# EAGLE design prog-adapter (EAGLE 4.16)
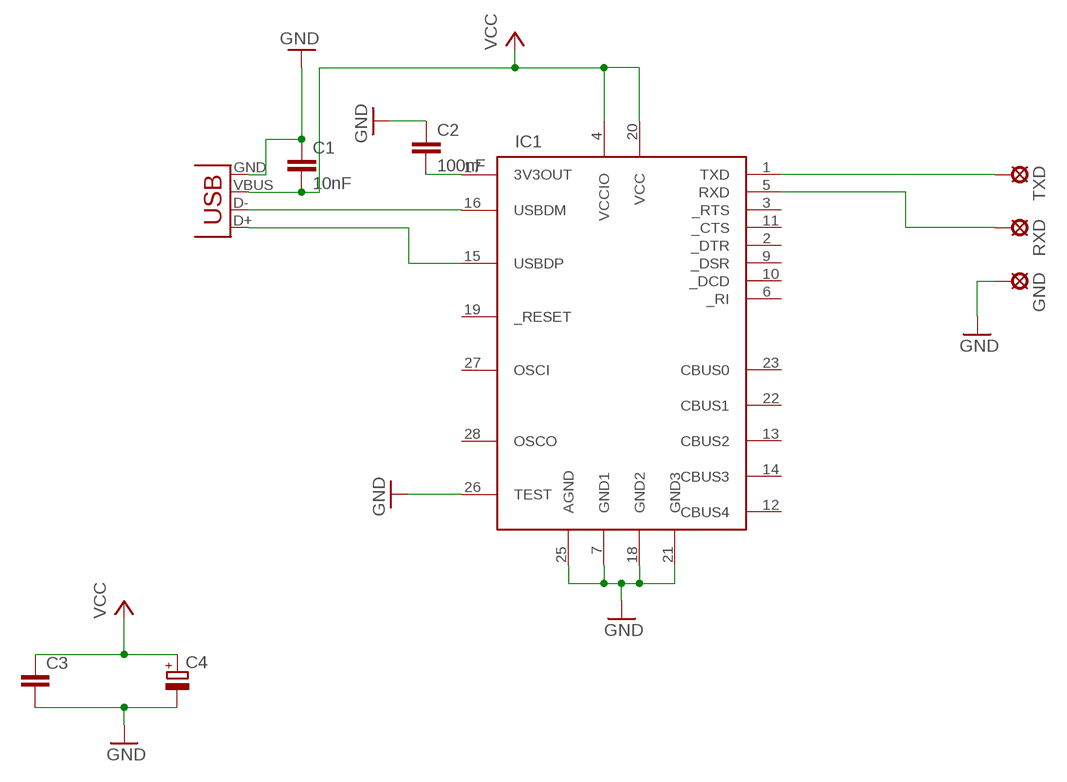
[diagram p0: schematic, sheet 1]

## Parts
C1  10nF  C-EUC1206  [C1206]
C2  100nF  C-EUC1206  [C1206]
C3  C-EUC1206  [C1206]
C4  CPOL-EUSMCC  [SMC_C]
GND  LSP10  [LSP10]
IC1  FT232RL  [SSOP28DB]
RXD  LSP10  [LSP10]
TXD  LSP10  [LSP10]
X1  USB-MB-S  [USB-MB-S]

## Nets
GND: C1.1 C2.1 C3.2 C4.- GND.MP IC1.7(GND1) IC1.18(GND2) IC1.21(GND3) IC1.25(AGND) IC1.26(TEST) X1.GND
N$1: IC1.16(USBDM) X1.D-
N$2: IC1.15(USBDP) X1.D+
N$3: IC1.1(TXD) TXD.MP
N$4: IC1.5(RXD) RXD.MP
N$6: C2.2 IC1.17(3V3OUT)
VCC: C1.2 C3.1 C4.+ IC1.4(VCCIO) IC1.20(VCC) X1.VBUS
Unconnected: IC1.2(_DTR) IC1.3(_RTS) IC1.6(_RI) IC1.9(_DSR) IC1.10(_DCD) IC1.11(_CTS) IC1.12(CBUS4) IC1.13(CBUS2) IC1.14(CBUS3) IC1.19(_RESET) IC1.22(CBUS1) IC1.23(CBUS0) IC1.27(OSCI) IC1.28(OSCO)

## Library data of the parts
C1-C3 = rcl:C-EU: CAPACITOR, European symbol
C4 = rcl:CPOL-EU: POLARIZED CAPACITOR, European symbol
GND RXD TXD = solpad:LSP10: SOLDER PAD
IC1 = ftdichip:FT232RL: USB UART 4th Generation USB UART (USB <-> Serial) Controller
X1 = con-usb:USB: USB Connectors

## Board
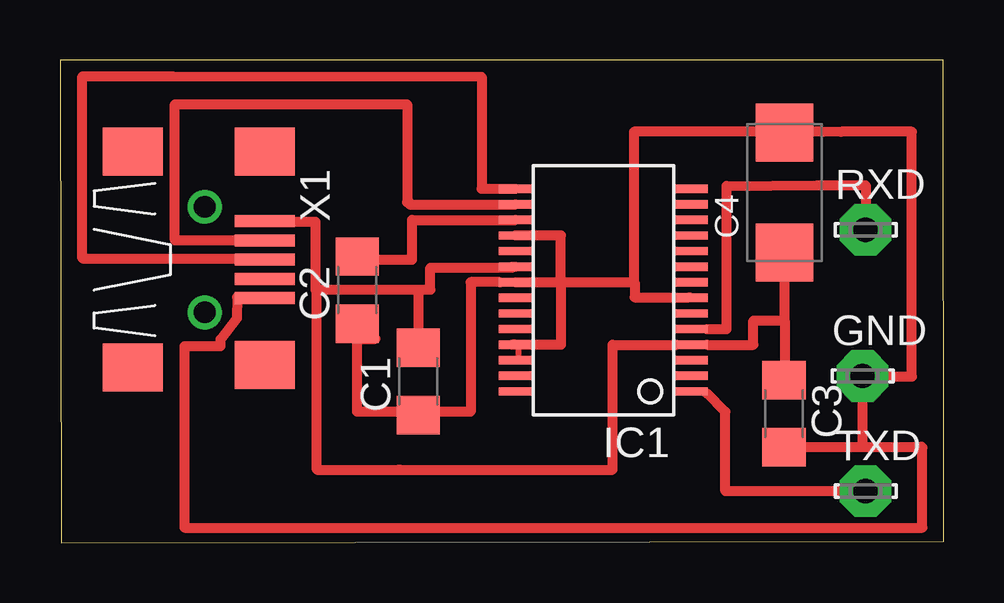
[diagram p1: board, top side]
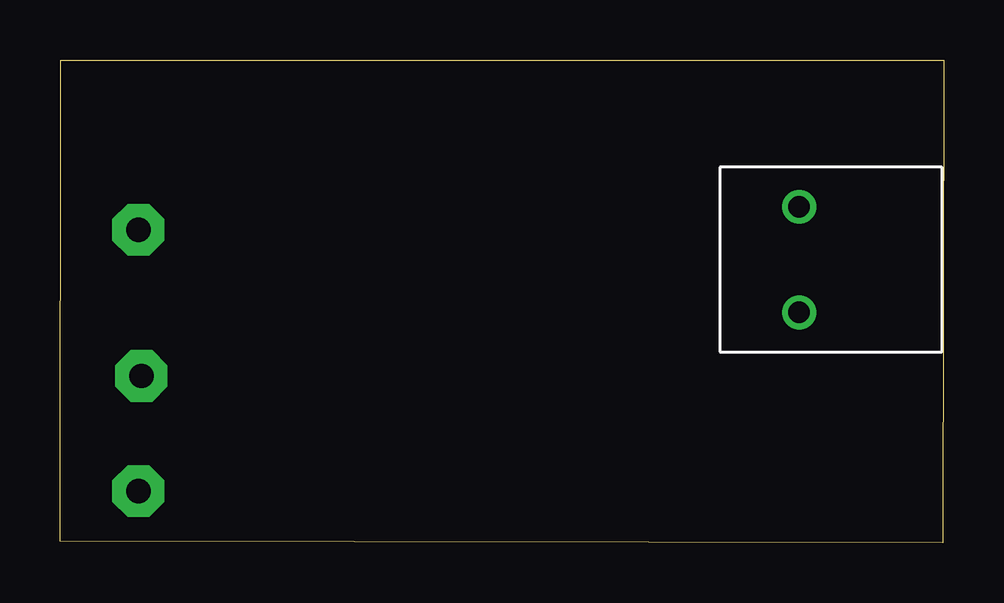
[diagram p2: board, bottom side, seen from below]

Size 36.83 x 20.13 mm. Coordinates in mm from the lower left corner, seen from the top.
Outline: 0.05,0 36.83,0.05 36.8,20.13 0,20.13 0.05,0
Copper layers (1*16): Top 0.035mm / dielectric 1.5mm / Bottom 0.035mm
Design rules "default": minimum track width 10mil, minimum drill 24mil, track to track 8mil, track to pad 8mil, pad to pad 8mil, via to via 8mil, smd to smd 8mil, copper to edge 40mil, drill to drill 8mil, minimum pad ring 10mil, minimum via ring 8mil, stop-mask expansion 4mil, vias tented up to drill 0mil, thermal gap 10mil

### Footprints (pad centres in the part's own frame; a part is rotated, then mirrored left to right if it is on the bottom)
C1206 = smd 1.6 x 1.8: 1 -1.4,0; 2 1.4,0
SMC_C = smd 2.4 x 2.4: + -2.5,0; - 2.5,0
LSP10 = drill 1.016 pad 2.159 octagon: MP 0,0
SSOP28DB = smd 0.348 x 1.397: 1 -4.225,-3.656; 2 -3.575,-3.656; 3 -2.925,-3.656; 4 -2.275,-3.656; 5 -1.625,-3.656; 6 -0.975,-3.656; 7 -0.325,-3.656; 8 0.325,-3.656; 9 0.975,-3.656; 10 1.625,-3.656; 11 2.275,-3.656; 12 2.925,-3.656; 13 3.575,-3.656; 14 4.225,-3.656; 15 4.225,3.656; 16 3.575,3.656; 17 2.925,3.656; 18 2.275,3.656; 19 1.625,3.656; 20 0.975,3.656; 21 0.325,3.656; 22 -0.325,3.656; 23 -0.975,3.656; 24 -1.625,3.656; 25 -2.275,3.656; 26 -2.925,3.656; 27 -3.575,3.656; 28 -4.225,3.656
USB-MB-S = smd 2.5 x 0.5: D+ 2.5,0; D- 2.5,0.8; GND 2.5,-1.6; ID 2.5,-0.8; VBUS 2.5,1.6 | smd 2.5 x 2: P$1 -3,-4.5; P$2 -3,4.5; P$3 2.5,-4.4; P$4 2.5,4.5 | drill 0.9 round: P$5 0,2.2; P$6 0,-2.2

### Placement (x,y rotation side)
C1  14.92,6.73 90 top
C2  12.38,10.54 90 top
C3  30.16,5.38 270 top
C4  30.19,14.6 90 top
GND  33.44,6.95 0 top
IC1  22.64,10.54 90 top
RXD  33.57,13.05 0 top
TXD  33.57,2.15 0 top
X1  6.03,11.81 0 top

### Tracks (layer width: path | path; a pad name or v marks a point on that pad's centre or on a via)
GND
  Top 0.254: 14.16,4.69 C1.1 15.68,4.69 | 13.14,8.5 C2.1 | IC1.26 19.09,7.74 19.09,8.25 IC1.25 | 26.23,10.23 IC1.7 | C4.- 31.79,17.14 | IC1.21 18.33,10.87
  Top 0.406: IC1.18 20.87,12.81 20.87,10.84 | 20.87,10.84 20.87,8.25 19.09,8.25 18.83,8.25 18.83,8.26 IC1.25 | C2.1 12.38,9.27 | IC1.21 20.87,10.86 20.87,10.84 | 20.87,10.84 20.87,10.79 | 23.91,10.84 20.87,10.84 | 31.79,17.14 23.91,17.14 23.91,10.84 | C4.- 32.55,17.14 35.5,17.14 35.5,6.93 33.44,6.93 | 13.14,8.5 12.38,8.5 12.38,5.46 14.92,5.46 | 18.33,10.87 17.11,10.87 17.11,5.46 14.92,5.46 | 14.92,5.46 C1.1 | 26.23,10.23 23.94,10.23 23.94,10.84 23.91,10.84 | 33.44,6.93 GND.MP | X1.GND 7.38,10.23 7.4,10.23 7.38,9.37 6.69,8.48 6.69,8.2 5.19,8.2 5.19,0.63 35.93,0.63 35.93,3.96 35.9,3.96 35.9,3.98 | 35.9,3.98 33.44,3.98 | 33.44,3.98 C3.2 | 35.9,3.98 35.9,4.01 | 33.44,3.98 33.44,6.93
N$1
  Top 0.406: X1.D- 8.45,12.61 8.45,12.62 4.79,12.62 4.79,18.28 14.47,18.28 14.47,14.19 14.57,14.19 14.57,14.11 IC1.16
N$2
  Top 0.406: IC1.15 17.56,14.76 17.56,19.43 4.71,19.45 0.93,19.45 0.93,11.86 8.47,11.86 8.47,11.81 X1.D+
N$3
  Top 0.254: 26.96,6.22 IC1.1
  Top 0.406: 26.96,6.22 27.72,5.46 27.72,2.15 TXD.MP
N$4
  Top 0.254: IC1.5 26.96,8.91
  Top 0.406: 26.96,8.91 27.77,8.91 27.77,14.88 31.53,14.9 33.57,14.9 RXD.MP
N$6
  Top 0.406: IC1.17 14.67,13.46 14.67,11.81 12.38,11.81 C2.2
VCC
  Top 0.254: 26.96,8.25 IC1.4 25.69,8.25
  Top 0.406: 14.92,10.56 15.43,10.56 15.43,11.48 18.83,11.48 18.83,11.51 IC1.20 | C3.1 30.19,6.73 30.19,9.27 | 14.92,10.56 C1.2 | 25.69,8.25 23.02,8.25 23.02,3.04 14.11,3.04 | 14.11,3.04 10.71,3.04 10.71,10.61 10.66,10.61 | 30.19,9.27 C4.+ | 14.11,3.04 14.16,3.04 | 26.96,8.25 28.89,8.25 28.89,9.27 30.19,9.27 | X1.VBUS 8.55,13.36 | X1.VBUS | 14.92,10.56 10.66,10.56 10.66,10.61 | 10.66,10.61 10.66,13.38 8.55,13.38 X1.VBUS | X1.VBUS 8.55,13.43 | X1.VBUS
